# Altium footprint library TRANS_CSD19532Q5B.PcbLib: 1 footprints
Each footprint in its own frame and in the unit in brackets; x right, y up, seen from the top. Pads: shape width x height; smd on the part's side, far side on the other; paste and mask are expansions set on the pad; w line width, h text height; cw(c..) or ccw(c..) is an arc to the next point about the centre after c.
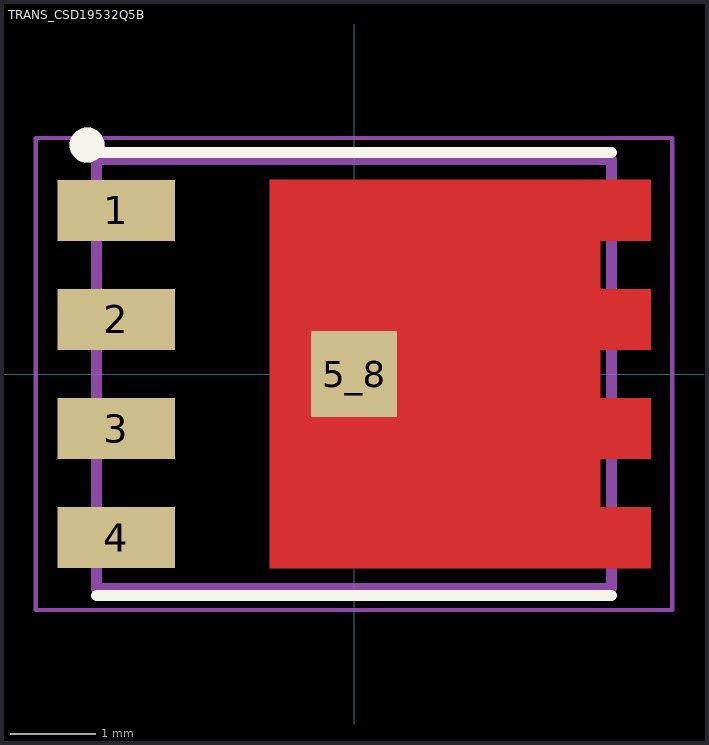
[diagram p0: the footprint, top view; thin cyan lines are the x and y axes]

## TRANS_CSD19532Q5B [mm]
height 1.05
pads (5):
  rect 1.372x0.71 smd paste-2 mask+0.05: 1(-2.77,1.905) 2(-2.77,0.635) 3(-2.77,-0.635) 4(-2.77,-1.905)
  rect 1x1 smd paste-1 mask+0: 5_8(0,0)
Top Layer:
  region: 3.456,1.55 2.866,1.55 2.866,0.99 3.456,0.99 3.456,0.28 2.866,0.28 2.866,-0.28 3.456,-0.28 3.456,-0.99 2.866,-0.99 2.866,-1.55 3.456,-1.55 3.456,-2.26 -0.984,-2.26 -0.984,2.26 3.456,2.26
Top Overlay:
  circle w0.254: c-3.109,2.667 r0.076
  lines w0.127: -3,-2.58 3,-2.58 ; -3,2.58 3,2.58
Top Paste:
  region: -2.221,1.624 -3.293,1.624 -3.293,2.186 -2.221,2.186
  region: -2.221,0.354 -3.293,0.354 -3.293,0.916 -2.221,0.916
  region: -2.221,-0.916 -3.293,-0.916 -3.293,-0.354 -2.221,-0.354
  region: -2.221,-2.186 -3.293,-2.186 -3.293,-1.624 -2.221,-1.624
  region: 3.293,1.651 2.527,1.651 2.527,2.159 3.293,2.159
  region: 3.293,0.381 2.527,0.381 2.527,0.889 3.293,0.889
  region: 3.293,-0.889 2.527,-0.889 2.527,-0.381 3.293,-0.381
  region: 3.293,-2.159 2.527,-2.159 2.527,-1.651 3.293,-1.651
  region: 2.241,0.15 0.947,0.15 0.947,0.896 2.241,0.896
  region: 2.241,-0.896 0.947,-0.896 0.947,-0.15 2.241,-0.15
  region: 2.241,1.196 0.947,1.196 0.947,1.942 2.241,1.942
  region: 2.241,-1.942 0.947,-1.942 0.947,-1.196 2.241,-1.196
  region: 0.597,-1.942 -0.697,-1.942 -0.697,-1.196 0.597,-1.196
  region: 0.597,-0.896 -0.697,-0.896 -0.697,-0.15 0.597,-0.15
  region: 0.597,0.15 -0.697,0.15 -0.697,0.896 0.597,0.896
  region: 0.597,1.196 -0.697,1.196 -0.697,1.942 0.597,1.942
Top Solder:
  region: 3.556,1.45 2.966,1.45 2.966,1.09 3.556,1.09 3.556,0.18 2.966,0.18 2.966,-0.18 3.556,-0.18 3.556,-1.09 2.966,-1.09 2.966,-1.45 3.556,-1.45 3.556,-2.36 -1.084,-2.36 -1.084,2.36 3.556,2.36
Mechanical 13:
  circle w0.254: c-3.109,2.667 r0.076
  lines w0.127: -3,-2.5 -3,2.5 3,2.5 3,-2.5 -3,-2.5
Mechanical 15:
  lines w0.05: -3.706,-2.75 3.706,-2.75 3.706,2.75 -3.706,2.75 -3.706,-2.75
3D body "step_temp.STEP": height 1.05, standoff 0, extent -3,-2.5 3,2.5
